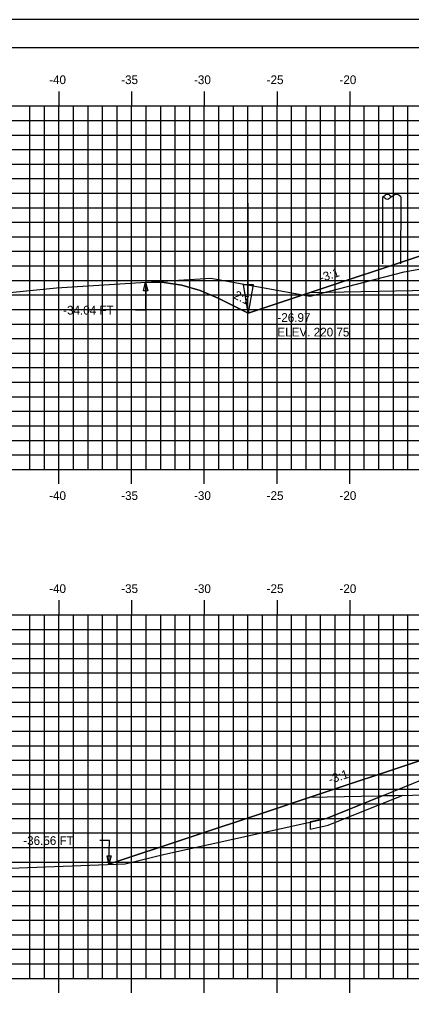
# Model space of a CAD drawing. Extents: x 1137654 to 1137824, y 608981 to 609091.
# Drawn here: x 1137694.7 to 1137721.7, y 609024.1 to 609091.3 of the extents above; entities that cross this region are included whole.
import ezdxf

# ---------------------------------------------------------------- set-up
doc = ezdxf.new("R2010")
doc.units = 0
for name, color, linetype in [('ANNOTATION', 7, 'Continuous'), ('BORDER', 7, 'Continuous'), ('D_Drainage_Ditch_Line', 7, 'Continuous'), ('D_Roadway_SlopeLines', 7, 'Continuous'), ('D_Roadway_SubGrade', 7, 'Continuous'), ('D_Text_Standard', 7, 'Continuous'), ('H_V ANNOTATION', 7, 'Continuous'), ('MAJOR', 7, 'Continuous'), ('MINOR', 7, 'Continuous'), ('PLOT BOUNDARY', 7, 'Continuous'), ('S_Roadway_Centerline', 7, 'Continuous'), ('S_Utilities_Pole_Power', 7, 'Continuous'), ('SHADING', 7, 'Continuous')]:
    doc.layers.add(name, color=color, linetype=linetype)

msp = doc.modelspace()

# ---------------------------------------------------------------- linework, layer by layer
for points in [[(1137703.372, 609073.203), (1137704.622, 609073.195), (1137705.872, 609073.01), (1137707.122, 609072.649), (1137708.372, 609072.113), (1137710.435, 609071.081), (1137714.685, 609072.498), (1137722.408, 609075.072), (1137722.409, 609075.072), (1137726.409, 609075.232), (1137737.409, 609075.452), (1137748.409, 609075.232), (1137761.476, 609074.71), (1137768.621, 609072.328), (1137772.371, 609071.078), (1137780.547, 609075.166), (1137781.797, 609075.675), (1137783.047, 609075.953), (1137784.297, 609075.999), (1137785.547, 609075.814)], [(1137700.848, 609033.177), (1137711.685, 609036.789), (1137714.685, 609037.789), (1137722.408, 609040.363), (1137722.409, 609040.363), (1137726.409, 609040.523), (1137737.409, 609040.743), (1137748.409, 609040.743), (1137755.981, 609040.44), (1137763.476, 609037.942), (1137766.476, 609036.942), (1137769.526, 609038.467), (1137770.776, 609039.018), (1137772.026, 609039.421), (1137773.276, 609039.676), (1137774.526, 609039.784)]]:
    msp.add_lwpolyline(points)
at = {"layer": 'BORDER'}
msp.add_lwpolyline([(1137662.41, 608984.335), (1137822.41, 608984.335), (1137822.41, 609089.335), (1137662.41, 609089.335)], close=True, dxfattribs=at)
at = {"layer": 'D_Drainage_Ditch_Line'}
msp.add_line((1137710.435, 609072.393), (1137710.435, 609078.637), dxfattribs=at)
msp.add_lwpolyline([(1137710.107, 609073.05), (1137710.763, 609073.05), (1137710.435, 609071.081)], close=True, dxfattribs=at)
at = {"layer": 'D_Roadway_SlopeLines'}
for points in [[(1137710.435, 609071.081), (1137708.372, 609072.113), (1137707.122, 609072.649), (1137705.872, 609073.01), (1137704.622, 609073.195), (1137703.372, 609073.203)], [(1137714.685, 609072.498), (1137710.435, 609071.081)], [(1137714.685, 609037.789), (1137711.685, 609036.789)], [(1137714.685, 609036.088), (1137714.685, 609035.588), (1137715.923, 609035.862), (1137721.007, 609037.915)], [(1137711.685, 609036.789), (1137700.848, 609033.177)]]:
    msp.add_lwpolyline(points, dxfattribs=at)
at = {"layer": 'D_Roadway_SubGrade'}
for points in [[(1137726.409, 609074.816), (1137726.409, 609074.982), (1137722.409, 609074.822), (1137722.409, 609075.072), (1137722.408, 609075.072), (1137714.685, 609072.498), (1137726.409, 609072.732)], [(1137726.409, 609040.107), (1137726.409, 609040.273), (1137722.409, 609040.113), (1137722.409, 609040.363), (1137722.408, 609040.363), (1137714.685, 609037.789), (1137726.409, 609038.023)]]:
    msp.add_lwpolyline(points, close=True, dxfattribs=at)
at = {"layer": 'D_Text_Standard'}
for points in [[(1137703.372, 609073.209), (1137703.361, 609071.288), (1137702.681, 609071.288)], [(1137700.848, 609033.177), (1137700.895, 609034.809), (1137700.215, 609034.809)]]:
    msp.add_lwpolyline(points, dxfattribs=at)
for points in [[(1137703.372, 609073.209), (1137703.514, 609072.626), (1137703.223, 609072.628)], [(1137700.848, 609033.177), (1137700.719, 609033.763), (1137701.01, 609033.754)]]:
    msp.add_lwpolyline(points, close=True, dxfattribs=at)
at = {"layer": 'MAJOR'}
for p, q in [((1137697.409, 609086.337), (1137697.409, 609085.335)), ((1137702.409, 609086.337), (1137702.409, 609085.335)), ((1137707.409, 609086.337), (1137707.409, 609085.335)), ((1137712.409, 609086.337), (1137712.409, 609085.335)), ((1137717.409, 609086.337), (1137717.409, 609085.335)), ((1137667.409, 609085.335), (1137807.409, 609085.335)), ((1137667.409, 609085.335), (1137807.409, 609085.335)), ((1137697.409, 609060.335), (1137697.409, 609085.335)), ((1137702.409, 609060.335), (1137702.409, 609085.335)), ((1137707.409, 609060.335), (1137707.409, 609085.335)), ((1137712.409, 609060.335), (1137712.409, 609085.335)), ((1137717.409, 609060.335), (1137717.409, 609085.335)), ((1137667.409, 609080.335), (1137807.409, 609080.335)), ((1137667.409, 609075.335), (1137807.409, 609075.335)), ((1137667.409, 609070.335), (1137807.409, 609070.335)), ((1137667.409, 609065.335), (1137807.409, 609065.335)), ((1137667.409, 609060.335), (1137807.409, 609060.335)), ((1137667.409, 609060.335), (1137807.409, 609060.335)), ((1137697.409, 609059.333), (1137697.409, 609060.335)), ((1137702.409, 609059.333), (1137702.409, 609060.335)), ((1137707.409, 609059.333), (1137707.409, 609060.335)), ((1137712.409, 609059.333), (1137712.409, 609060.335)), ((1137717.409, 609059.333), (1137717.409, 609060.335)), ((1137697.409, 609051.337), (1137697.409, 609050.335)), ((1137702.409, 609051.337), (1137702.409, 609050.335)), ((1137707.409, 609051.337), (1137707.409, 609050.335)), ((1137712.409, 609051.337), (1137712.409, 609050.335)), ((1137717.409, 609051.337), (1137717.409, 609050.335)), ((1137667.409, 609050.335), (1137807.409, 609050.335)), ((1137667.409, 609050.335), (1137807.409, 609050.335)), ((1137697.409, 609025.335), (1137697.409, 609050.335)), ((1137702.409, 609025.335), (1137702.409, 609050.335)), ((1137707.409, 609025.335), (1137707.409, 609050.335)), ((1137712.409, 609025.335), (1137712.409, 609050.335)), ((1137717.409, 609025.335), (1137717.409, 609050.335)), ((1137667.409, 609045.335), (1137807.409, 609045.335)), ((1137667.409, 609040.335), (1137807.409, 609040.335)), ((1137667.409, 609035.335), (1137807.409, 609035.335)), ((1137667.409, 609030.335), (1137807.409, 609030.335)), ((1137667.409, 609025.335), (1137807.409, 609025.335)), ((1137667.409, 609025.335), (1137807.409, 609025.335)), ((1137697.409, 609024.333), (1137697.409, 609025.335)), ((1137702.409, 609024.333), (1137702.409, 609025.335)), ((1137707.409, 609024.333), (1137707.409, 609025.335)), ((1137712.409, 609024.333), (1137712.409, 609025.335)), ((1137717.409, 609024.333), (1137717.409, 609025.335))]:
    msp.add_line(p, q, dxfattribs=at)
at = {"layer": 'MINOR'}
for p, q in [((1137695.409, 609060.335), (1137695.409, 609085.335)), ((1137696.409, 609060.335), (1137696.409, 609085.335)), ((1137698.409, 609060.335), (1137698.409, 609085.335)), ((1137699.409, 609060.335), (1137699.409, 609085.335)), ((1137700.409, 609060.335), (1137700.409, 609085.335)), ((1137701.409, 609060.335), (1137701.409, 609085.335)), ((1137703.409, 609060.335), (1137703.409, 609085.335)), ((1137704.409, 609060.335), (1137704.409, 609085.335)), ((1137705.409, 609060.335), (1137705.409, 609085.335)), ((1137706.409, 609060.335), (1137706.409, 609085.335)), ((1137708.409, 609060.335), (1137708.409, 609085.335)), ((1137709.409, 609060.335), (1137709.409, 609085.335)), ((1137710.409, 609060.335), (1137710.409, 609085.335)), ((1137711.409, 609060.335), (1137711.409, 609085.335)), ((1137713.409, 609060.335), (1137713.409, 609085.335)), ((1137714.409, 609060.335), (1137714.409, 609085.335)), ((1137715.409, 609060.335), (1137715.409, 609085.335)), ((1137716.409, 609060.335), (1137716.409, 609085.335)), ((1137718.409, 609060.335), (1137718.409, 609085.335)), ((1137719.409, 609060.335), (1137719.409, 609085.335)), ((1137720.409, 609060.335), (1137720.409, 609085.335)), ((1137721.409, 609060.335), (1137721.409, 609085.335)), ((1137667.409, 609084.335), (1137807.409, 609084.335)), ((1137667.409, 609083.335), (1137807.409, 609083.335)), ((1137667.409, 609082.335), (1137807.409, 609082.335)), ((1137667.409, 609081.335), (1137807.409, 609081.335)), ((1137667.409, 609079.335), (1137807.409, 609079.335)), ((1137667.409, 609078.335), (1137807.409, 609078.335)), ((1137667.409, 609077.335), (1137807.409, 609077.335)), ((1137667.409, 609076.335), (1137807.409, 609076.335)), ((1137667.409, 609074.335), (1137807.409, 609074.335)), ((1137667.409, 609073.335), (1137807.409, 609073.335)), ((1137667.409, 609072.335), (1137807.409, 609072.335)), ((1137667.409, 609071.335), (1137807.409, 609071.335)), ((1137667.409, 609069.335), (1137807.409, 609069.335)), ((1137667.409, 609068.335), (1137807.409, 609068.335)), ((1137667.409, 609067.335), (1137807.409, 609067.335)), ((1137667.409, 609066.335), (1137807.409, 609066.335)), ((1137667.409, 609064.335), (1137807.409, 609064.335)), ((1137667.409, 609063.335), (1137807.409, 609063.335)), ((1137667.409, 609062.335), (1137807.409, 609062.335)), ((1137667.409, 609061.335), (1137807.409, 609061.335)), ((1137695.409, 609025.335), (1137695.409, 609050.335)), ((1137696.409, 609025.335), (1137696.409, 609050.335)), ((1137698.409, 609025.335), (1137698.409, 609050.335)), ((1137699.409, 609025.335), (1137699.409, 609050.335)), ((1137700.409, 609025.335), (1137700.409, 609050.335)), ((1137701.409, 609025.335), (1137701.409, 609050.335)), ((1137703.409, 609025.335), (1137703.409, 609050.335)), ((1137704.409, 609025.335), (1137704.409, 609050.335)), ((1137705.409, 609025.335), (1137705.409, 609050.335)), ((1137706.409, 609025.335), (1137706.409, 609050.335)), ((1137708.409, 609025.335), (1137708.409, 609050.335)), ((1137709.409, 609025.335), (1137709.409, 609050.335)), ((1137710.409, 609025.335), (1137710.409, 609050.335)), ((1137711.409, 609025.335), (1137711.409, 609050.335)), ((1137713.409, 609025.335), (1137713.409, 609050.335)), ((1137714.409, 609025.335), (1137714.409, 609050.335)), ((1137715.409, 609025.335), (1137715.409, 609050.335)), ((1137716.409, 609025.335), (1137716.409, 609050.335)), ((1137718.409, 609025.335), (1137718.409, 609050.335)), ((1137719.409, 609025.335), (1137719.409, 609050.335)), ((1137720.409, 609025.335), (1137720.409, 609050.335)), ((1137721.409, 609025.335), (1137721.409, 609050.335)), ((1137667.409, 609049.335), (1137807.409, 609049.335)), ((1137667.409, 609048.335), (1137807.409, 609048.335)), ((1137667.409, 609047.335), (1137807.409, 609047.335)), ((1137667.409, 609046.335), (1137807.409, 609046.335)), ((1137667.409, 609044.335), (1137807.409, 609044.335)), ((1137667.409, 609043.335), (1137807.409, 609043.335)), ((1137667.409, 609042.335), (1137807.409, 609042.335)), ((1137667.409, 609041.335), (1137807.409, 609041.335)), ((1137667.409, 609039.335), (1137807.409, 609039.335)), ((1137667.409, 609038.335), (1137807.409, 609038.335)), ((1137667.409, 609037.335), (1137807.409, 609037.335)), ((1137667.409, 609036.335), (1137807.409, 609036.335)), ((1137667.409, 609034.335), (1137807.409, 609034.335)), ((1137667.409, 609033.335), (1137807.409, 609033.335)), ((1137667.409, 609032.335), (1137807.409, 609032.335)), ((1137667.409, 609031.335), (1137807.409, 609031.335)), ((1137667.409, 609029.335), (1137807.409, 609029.335)), ((1137667.409, 609028.335), (1137807.409, 609028.335)), ((1137667.409, 609027.335), (1137807.409, 609027.335)), ((1137667.409, 609026.335), (1137807.409, 609026.335))]:
    msp.add_line(p, q, dxfattribs=at)
at = {"layer": 'PLOT BOUNDARY'}
msp.add_lwpolyline([(1137654.316, 608981.276), (1137824.316, 608981.276), (1137824.316, 609091.276), (1137654.316, 609091.276)], close=True, dxfattribs=at)
at = {"layer": 'S_Roadway_Centerline'}
for points in [[(1137667.409, 609069.72), (1137676.984, 609070.875), (1137687.338, 609071.833), (1137697.235, 609072.821), (1137703.411, 609073.206), (1137707.864, 609073.49), (1137714.699, 609072.26), (1137721.151, 609073.928), (1137723.806, 609074.396), (1137725.924, 609074.671), (1137726.331, 609074.705), (1137728.139, 609074.727), (1137737.517, 609074.967), (1137739.695, 609074.987), (1137747.943, 609075.052), (1137748.455, 609075.015), (1137749.9, 609074.851), (1137752.206, 609074.198), (1137752.624, 609074.067), (1137753.307, 609074.115), (1137755.515, 609074.146), (1137758.076, 609075.005), (1137759.89, 609075.513), (1137770.942, 609076.182)], [(1137667.409, 609031.673), (1137680.898, 609032.377), (1137683.689, 609032.524), (1137701.957, 609033.219), (1137704.697, 609033.873), (1137715.818, 609036.339), (1137722.54, 609039.054), (1137724.51, 609039.355), (1137725.115, 609039.434), (1137727.86, 609039.504), (1137736.081, 609039.689), (1137744.308, 609039.789), (1137746.709, 609039.808), (1137746.997, 609039.677), (1137753.261, 609039.323), (1137761.612, 609039.363), (1137761.894, 609039.317), (1137766.806, 609039.577), (1137782.426, 609039.995), (1137793.11, 609040.238), (1137799.729, 609040.508), (1137807.409, 609040.788)]]:
    msp.add_lwpolyline(points, dxfattribs=at)
at = {"layer": 'S_Utilities_Pole_Power'}
for p, q in [((1137719.686, 609079.093), (1137719.842, 609079.204)), ((1137720.155, 609079.204), (1137720.312, 609079.093)), ((1137720.468, 609079.204), (1137720.312, 609079.093)), ((1137720.936, 609079.093), (1137720.78, 609079.204)), ((1137719.686, 609074.474), (1137719.69, 609079.093)), ((1137719.842, 609078.982), (1137719.686, 609079.093)), ((1137720.312, 609079.093), (1137720.155, 609078.982)), ((1137720.936, 609074.474), (1137720.94, 609079.093))]:
    msp.add_line(p, q, dxfattribs=at)
for centre, start, end in [((1137719.999, 609078.983), 90, 125.26439), ((1137719.999, 609078.983), 54.73561, 90), ((1137720.624, 609078.983), 90, 125.26439), ((1137720.624, 609078.983), 54.73561, 90), ((1137719.999, 609079.204), 234.73561, 270), ((1137719.999, 609079.204), 270, 305.26439)]:
    msp.add_arc(centre, 0.271, start, end, dxfattribs=at)
at = {"layer": 'SHADING'}
msp.add_line((1137721.007, 609037.915), (1137719.654, 609037.888), dxfattribs=at)
for points in [[(1137714.685, 609036.088), (1137714.685, 609035.588), (1137715.923, 609035.862), (1137721.007, 609037.915)], [(1137719.654, 609037.888), (1137715.818, 609036.339), (1137714.685, 609036.088)]]:
    msp.add_lwpolyline(points, dxfattribs=at)

# ---------------------------------------------------------------- texts
at = {"layer": 'ANNOTATION'}
for s, rotation, p in [('-3:1', 18.43484, (1137715.439, 609073.203)), ('2:1', 333.43495, (1137709.37, 609072.131)), ('-3:1', 18.43482, (1137716.064, 609038.703))]:
    msp.add_text(s, height=0.6, rotation=rotation, dxfattribs=at).set_placement(p)
at = {"layer": 'D_Text_Standard'}
for s, p in [('-34.04 FT', (1137697.697, 609070.988)), ('-26.97', (1137712.435, 609070.481)), ('ELEV. 220.75', (1137712.435, 609069.479)), ('-36.56 FT', (1137694.953, 609034.509))]:
    msp.add_text(s, height=0.6, dxfattribs=at).set_placement(p)
at = {"layer": 'H_V ANNOTATION'}
for s, p in [('-40', (1137696.735, 609086.835)), ('-35', (1137701.69, 609086.835)), ('-30', (1137706.698, 609086.835)), ('-25', (1137711.695, 609086.835)), ('-20', (1137716.703, 609086.835)), ('-40', (1137696.735, 609058.235)), ('-35', (1137701.69, 609058.235)), ('-30', (1137706.698, 609058.235)), ('-25', (1137711.695, 609058.235)), ('-20', (1137716.703, 609058.235)), ('-40', (1137696.735, 609051.835)), ('-35', (1137701.69, 609051.835)), ('-30', (1137706.698, 609051.835)), ('-25', (1137711.695, 609051.835)), ('-20', (1137716.703, 609051.835))]:
    msp.add_text(s, height=0.6, dxfattribs=at).set_placement(p)

doc.saveas('drawing.dxf')
